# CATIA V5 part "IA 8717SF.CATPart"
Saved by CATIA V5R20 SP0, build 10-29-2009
Part number: IA 8717SF
Revision: ANY
Definition: UNKNOWN
Nomenclature: IA 8717SF
Source: Unknown
Bounding box of the stored display mesh (mm): x -4.35 to 4.35, y -17 to 0, z -4.35 to 4.35
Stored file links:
  C:\Users\Utente\Desktop\IO LAVORO\3D X SITO CF\CUMSA\3D files IA\IA 8717SF\IA 8717SF.CATPart
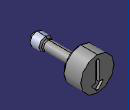
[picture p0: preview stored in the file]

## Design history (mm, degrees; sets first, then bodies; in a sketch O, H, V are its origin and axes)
Body1 "Cortar-Extruir1" (main body)
  Solid1: solid without history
